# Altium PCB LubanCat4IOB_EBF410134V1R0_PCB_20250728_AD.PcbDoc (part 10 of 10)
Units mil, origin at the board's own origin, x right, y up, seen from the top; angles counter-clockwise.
Board outline 5236.21 x 4055.11 mil, 6 copper layers (TOP, GND02, ART03, PWR04, GND05, BOTTOM), stack 47.2 mil thick; 614 components, 490 nets, 2311 pads, 1916 vias.
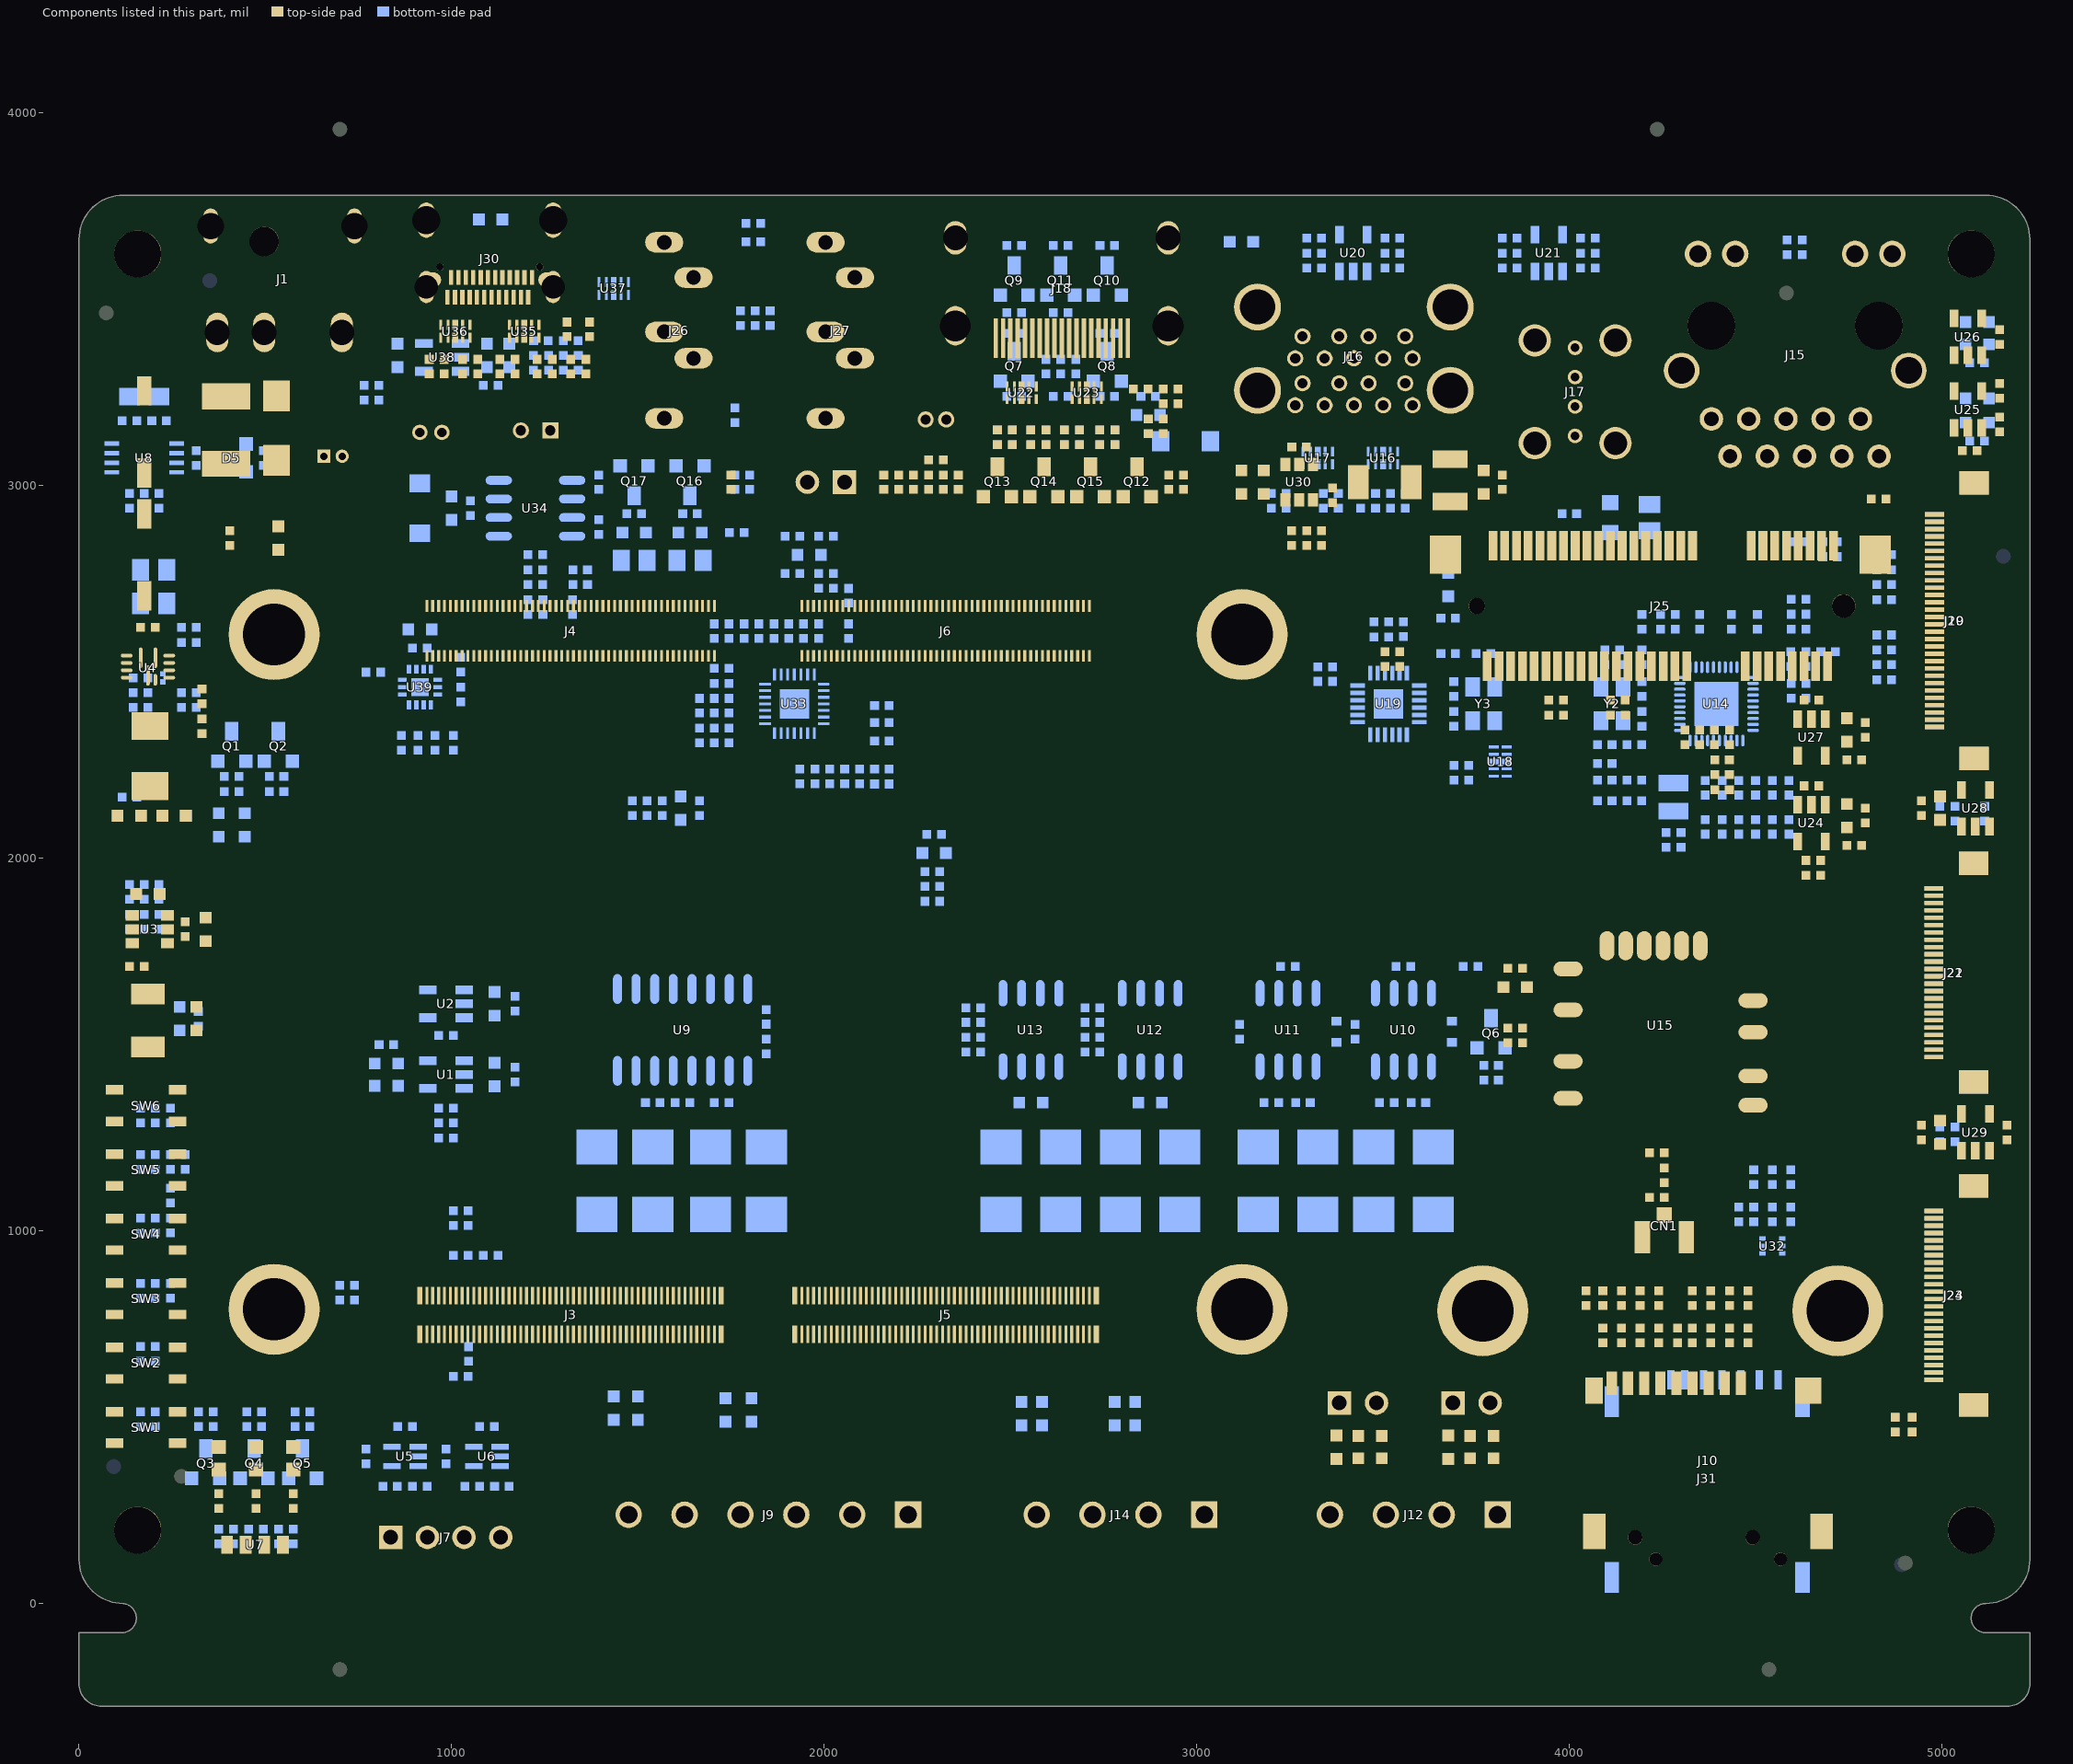
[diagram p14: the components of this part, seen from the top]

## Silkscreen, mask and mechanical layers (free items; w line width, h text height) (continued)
NCLEGEND-1-6:
  circle w1: c6914,1957.37 r23.62
  lines w1: 6464.5,-2917.63 13191.5,-2917.63 ; 6464.5,-2667.63 13191.5,-2667.63 ; 6464.5,-2417.63 13191.5,-2417.63 ; 6464.5,-2167.63 13191.5,-2167.63 ; 6464.5,-1917.63 13191.5,-1917.63 ; 6464.5,-1667.63 13191.5,-1667.63 ; 6464.5,-1417.63 13191.5,-1417.63 ; 6464.5,-1167.63 13191.5,-1167.63 ; 6464.5,-917.63 13191.5,-917.63 ; 6464.5,-667.63 13191.5,-667.63 ; 6464.5,-417.63 13191.5,-417.63 ; 6464.5,-167.63 13191.5,-167.63 ; 6464.5,82.37 13191.5,82.37 ; 6464.5,332.37 13191.5,332.37 ; 6464.5,582.37 13191.5,582.37 ; 6464.5,832.37 13191.5,832.37 ; 6464.5,1082.37 13191.5,1082.37 ; 6464.5,1332.37 13191.5,1332.37 ; 6464.5,1582.37 13191.5,1582.37 ; 6464.5,1832.37 13191.5,1832.37 ; 6464.5,2082.37 13191.5,2082.37 ; 6464.5,2332.37 13191.5,2332.37 ; 6464.5,2582.37 13191.5,2582.37 ; 6464.5,2832.37 13191.5,2832.37 ; 6464.5,3082.37 13191.5,3082.37 ; 6464.5,3332.37 13191.5,3332.37 ; 6464.5,3582.37 13191.5,3582.37 ; 6464.5,3832.37 13191.5,3832.37 ; 6464.5,4082.37 13191.5,4082.37 ; 6464.5,4332.37 13191.5,4332.37 ; 6464.5,4582.37 13191.5,4582.37 ; 6464.5,4832.37 13191.5,4832.37 ; 6464.5,5082.37 13191.5,5082.37 ; 6909,4457.37 6919,4457.37 ; 6914,4452.37 6914,4462.37 ; 7363.5,-3167.63 7363.5,4832.37 ; 9254.5,-3167.63 9254.5,4832.37 ; 11145.5,-3167.63 11145.5,4832.37 ; 12416.5,-3167.63 12416.5,4832.37 ; 6464.5,-3167.63 6464.5,5332.37 13191.5,5332.37 13191.5,-3167.63 6464.5,-3167.63 ; 6884.17,3457.37 6892.91,3436.28 6914,3427.54 6935.09,3436.28 6943.83,3457.37 6935.09,3478.46 6914,3487.2 6892.91,3478.46 6884.17,3457.37 ; 6884.47,2452.45 ccw(c6914,2452.45) 6943.53,2452.45 6943.53,2462.29 ccw(c6914,2462.29) 6884.47,2462.29 6884.47,2452.45 ; 6886.4,-2308.33 ccw(c6886.4,-2292.63) 6886.4,-2276.93 6941.6,-2276.93 ccw(c6941.6,-2292.63) 6941.6,-2308.33 6886.4,-2308.33 ; 6888.41,-2566.25 ccw(c6888.41,-2542.63) 6888.41,-2519.01 6939.59,-2519.01 ccw(c6939.59,-2542.63) 6939.59,-2566.25 6888.41,-2566.25 ; 6890,-3077.63 ccw(c6890,-3042.63) 6890,-3007.63 6938,-3007.63 ccw(c6938,-3042.63) 6938,-3077.63 6890,-3077.63 ; 6890.38,-2062.32 ccw(c6890.38,-2042.63) 6890.38,-2022.95 6937.62,-2022.94 ccw(c6937.62,-2042.63) 6937.62,-2062.32 6890.38,-2062.32 ; 6894.31,-2832 ccw(c6894.31,-2792.63) 6894.31,-2753.26 6933.69,-2753.26 ccw(c6933.69,-2792.63) 6933.69,-2832 6894.31,-2832 ; 6894.31,-1566.25 ccw(c6894.31,-1542.63) 6894.31,-1519.01 6933.69,-1519.01 ccw(c6933.69,-1542.63) 6933.69,-1566.25 6894.31,-1566.25 ; 6894.31,2187.68 6914,2227.05 6933.69,2187.68 6894.31,2187.68 ; 6894.31,2942.61 6894.31,2972.13 6933.69,2972.13 6933.69,2942.61 6894.31,2942.61 ; 6898.5,-1827.63 ccw(c6898.5,-1792.63) 6898.5,-1757.63 6929.5,-1757.63 ccw(c6929.5,-1792.63) 6929.5,-1827.63 6898.5,-1827.63 ; 6900.22,-1312.32 ccw(c6900.22,-1292.63) 6900.22,-1272.95 6927.78,-1272.94 ccw(c6927.78,-1292.63) 6927.78,-1312.32 6900.22,-1312.32 ; 6900.22,3207.37 6914,3221.15 6927.78,3207.37 6914,3193.59 6900.22,3207.37 ; 6901.2,3700.97 6914,3694.57 6926.8,3700.97 6926.8,3713.77 6914,3720.17 6901.2,3713.77 6901.2,3700.97 ; 6902.19,3957.37 6908.09,3945.56 6919.91,3945.56 6925.81,3957.37 6919.91,3969.18 6908.09,3969.18 6902.19,3957.37 ; 6904.16,4197.53 6923.84,4197.53 6923.84,4217.21 6904.16,4217.21 6904.16,4197.53 ; 6909.08,2677.84 ccw(c6909.08,2707.37) 6909.08,2736.9 6918.92,2736.9 ccw(c6918.92,2707.37) 6918.92,2677.84 6909.08,2677.84
  text "DRILL CHART: TOP to BOTTOM" at 8528,5144.87 h125
  text "ALL UNITS ARE IN MILS" at 8778,4894.87 h125
  text "FIGURE" at 6614,4644.87 h125
  text "SIZE" at 8109,4644.87 h125
  text "TOLERANCE" at 9750,4644.87 h125
  text "PLATED" at 11481,4644.87 h125
  text "QTY" at 12654,4644.87 h125
  text "10.0" at 8109,4394.87 h125
  text "+0.0/-0.0" at 9750,4394.87 h125
  text "PLATED" at 11481,4394.87 h125
  text "1913" at 12604,4394.87 h125
  text "19.685" at 8009,4144.87 h125
  text "+0.0/-0.0" at 9750,4144.87 h125
  text "PLATED" at 11481,4144.87 h125
  text "2" at 12754,4144.87 h125
  text "23.622" at 8009,3894.87 h125
  text "+0.0/-0.0" at 9750,3894.87 h125
  text "PLATED" at 11481,3894.87 h125
  text "4" at 12754,3894.87 h125
  text "25.591" at 8009,3644.87 h125
  text "+0.0/-0.0" at 9750,3644.87 h125
  text "PLATED" at 11481,3644.87 h125
  text "2" at 12754,3644.87 h125
  text "27.559" at 8009,3394.87 h125
  text "+0.0/-0.0" at 9750,3394.87 h125
  text "PLATED" at 11481,3394.87 h125
  text "18" at 12704,3394.87 h125
  text "27.559" at 8009,3144.87 h125
  text "+0.0/-0.0" at 9750,3144.87 h125
  text "PLATED" at 11481,3144.87 h125
  text "4" at 12754,3144.87 h125
  text "39.37" at 8059,2894.87 h125
  text "+0.0/-0.0" at 9750,2894.87 h125
  text "PLATED" at 11481,2894.87 h125
  text "13" at 12704,2894.87 h125
  text "39.37" at 8059,2644.87 h125
  text "+0.0/-0.0" at 9750,2644.87 h125
  text "PLATED" at 11481,2644.87 h125
  text "1" at 12754,2644.87 h125
  text "39.37" at 8059,2394.87 h125
  text "+0.0/-0.0" at 9750,2394.87 h125
  text "PLATED" at 11481,2394.87 h125
  text "3" at 12754,2394.87 h125
  text "39.37" at 8059,2144.87 h125
  text "+0.0/-0.0" at 9750,2144.87 h125
  text "PLATED" at 11481,2144.87 h125
  text "3" at 12754,2144.87 h125
  text "47.244" at 8009,1894.87 h125
  text "+0.0/-0.0" at 9750,1894.87 h125
  text "PLATED" at 11481,1894.87 h125
  text "18" at 12704,1894.87 h125
  text "62.992" at 8009,1644.87 h125
  text "+0.0/-0.0" at 9750,1644.87 h125
  text "PLATED" at 11481,1644.87 h125
  text "4" at 12754,1644.87 h125
  text "72.047" at 8009,1394.87 h125
  text "+0.0/-0.0" at 9750,1394.87 h125
  text "PLATED" at 11481,1394.87 h125
  text "2" at 12754,1394.87 h125
  text "94.5" at 8109,1144.87 h125
  text "+0.0/-0.0" at 9750,1144.87 h125
  text "PLATED" at 11481,1144.87 h125
  text "4" at 12754,1144.87 h125
  text "166.142" at 7959,894.87 h125
  text "+0.0/-0.0" at 9750,894.87 h125
  text "PLATED" at 11481,894.87 h125
  text "6" at 12754,894.87 h125
  text "19.685" at 8009,644.87 h125
  text "+0.0/-0.0" at 9750,644.87 h125
  text "NON-PLATED" at 11281,644.87 h125
  text "2" at 12754,644.87 h125
  text "35.433" at 8009,394.87 h125
  text "+0.0/-0.0" at 9750,394.87 h125
  text "NON-PLATED" at 11281,394.87 h125
  text "2" at 12754,394.87 h125
  text "39.37" at 8059,144.87 h125
  text "+0.0/-0.0" at 9750,144.87 h125
  text "NON-PLATED" at 11281,144.87 h125
  text "2" at 12754,144.87 h125
  text "43.307" at 8009,-105.13 h125
  text "+0.0/-0.0" at 9750,-105.13 h125
  text "NON-PLATED" at 11281,-105.13 h125
  text "1" at 12754,-105.13 h125
  text "62.992" at 8009,-355.13 h125
  text "+0.0/-0.0" at 9750,-355.13 h125
  text "NON-PLATED" at 11281,-355.13 h125
  text "1" at 12754,-355.13 h125
  text "78.701" at 8009,-605.13 h125
  text "+0.0/-0.0" at 9750,-605.13 h125
  text "NON-PLATED" at 11281,-605.13 h125
  text "1" at 12754,-605.13 h125
  text "125.984" at 7959,-855.13 h125
  text "+0.0/-0.0" at 9750,-855.13 h125
  text "NON-PLATED" at 11281,-855.13 h125
  text "4" at 12754,-855.13 h125
  text "127.953" at 7959,-1105.13 h125
  text "+0.0/-0.0" at 9750,-1105.13 h125
  text "NON-PLATED" at 11281,-1105.13 h125
  text "2" at 12754,-1105.13 h125
  text "47.244x19.685" at 7659,-1355.13 h125
  text "+0.0/-0.0" at 9750,-1355.13 h125
  text "PLATED" at 11481,-1355.13 h125
  text "2" at 12754,-1355.13 h125
  text "62.992x23.622" at 7659,-1605.13 h125
  text "+0.0/-0.0" at 9750,-1605.13 h125
  text "PLATED" at 11481,-1605.13 h125
  text "2" at 12754,-1605.13 h125
  text "66.0x35.0" at 7859,-1855.13 h125
  text "+3.0/-3.0" at 9750,-1855.13 h125
  text "PLATED" at 11481,-1855.13 h125
  text "2" at 12754,-1855.13 h125
  text "66.929x19.685" at 7659,-2105.13 h125
  text "+0.0/-0.0" at 9750,-2105.13 h125
  text "PLATED" at 11481,-2105.13 h125
  text "3" at 12754,-2105.13 h125
  text "70.902x15.701" at 7659,-2355.13 h125
  text "+0.0/-0.0" at 9750,-2355.13 h125
  text "PLATED" at 11481,-2355.13 h125
  text "2" at 12754,-2355.13 h125
  text "74.803x23.622" at 7659,-2605.13 h125
  text "+0.0/-0.0" at 9750,-2605.13 h125
  text "PLATED" at 11481,-2605.13 h125
  text "2" at 12754,-2605.13 h125
  text "78.74x39.37" at 7759,-2855.13 h125
  text "+0.0/-0.0" at 9750,-2855.13 h125
  text "PLATED" at 11481,-2855.13 h125
  text "10" at 12704,-2855.13 h125
  text "83.0x35.0" at 7859,-3105.13 h125
  text "+3.0/-3.0" at 9750,-3105.13 h125
  text "PLATED" at 11481,-3105.13 h125
  text "2" at 12754,-3105.13 h125
DRAWING_ORIGIN:
  lines w1: -25,0 25,0 ; 0,-25 0,25
ASSEMBLY_TOP:
  lines w5.91: 118.11,-78.74 433.07,-78.74 ; 118.11,0 433.07,0 ; 118.11,3779.52 433.07,3779.52 ; 118.11,3858.26 433.07,3858.26 ; 2460.62,-78.74 2775.59,-78.74 ; 2460.62,0 2775.59,0 ; 2460.62,3779.52 2775.59,3779.52 ; 2460.62,3858.26 2775.59,3858.26 ; 4803.14,-78.74 5118.1,-78.74 ; 4803.14,0 5118.1,0 ; 4803.14,3779.52 5118.1,3779.52 ; 4803.14,3858.26 5118.1,3858.26
Mechanical 255:
  lines w1: 855,2484.37 2400,2484.37 2395,2479.37 2395,2354.37 2440,2309.37 2660,2309.37 2800,2449.37 2800,2484.37 2800,2804.37 855,2804.37 855,2484.37 ; 875,639.37 2325,639.37 2325,489.37 2525,489.37 2525,639.37 2825,639.37 2825,939.37 1770,939.37 1770,1249.37 1710,1309.37 1405,1309.37 1350,1254.37 1350,939.37 875,939.37 875,639.37 ; 975,3459.37 1240,3459.37 1240,3616.37 975,3616.37 975,3459.37 ; 1225,3634.37 1330,3634.37 1330,3684.37 1225,3684.37 1225,3634.37 ; 1800,2294.37 2070,2294.37 2070,2544.37 1800,2544.37 1800,2294.37 ; 4240,2229.37 4615,2229.37 4615,2539.37 4240,2539.37 4240,2229.37 ; 4290,2480 4520,2480 4520,2625 4290,2625 4290,2480 ; 5015,2664.37 5130,2664.37 5130,2779.37 5015,2779.37 5015,2664.37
